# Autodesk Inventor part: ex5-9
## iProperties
Author: Administrator
Created: 2001-09
Part Number: ex5-9
Document SubType Name: Modeling
Designer: Administrator
Control State: 0
Master: False
Checked Out: False
PropertySet Name: Design Tracking Control
Length Units: 11272
Angle Units: 11279
Time Units: 11290
Mass Units: 11286
Shininess: 3
Angle Display Precision: 2
Document Length Units: 11272
Document Angle Units: 11286
Document Time Units: 11279
Document Mass Units: 11290
Document Length Units Precision: 3
Document Angle Units Precision: 2
Compacted: False
PropertySet Name: _Private Model Information
Density: 0.0
Volumn: 0.0
Area: 0.0
PropertySet Name: Model Information
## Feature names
1. Revolution1
2. Hole1
3. Shell1
4. Loft1
5. Sweep1
6. Coil1
7. Fillet1
